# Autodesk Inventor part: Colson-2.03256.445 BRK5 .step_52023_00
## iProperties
Created: 2010-10
Part Number: Colson-2.03256.445 BRK5 .step_52023_00
Document SubType Name: Modeling
Designer: Administrator
Density: 1 g/cm^3
Author: Administrator
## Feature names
1. Base1
